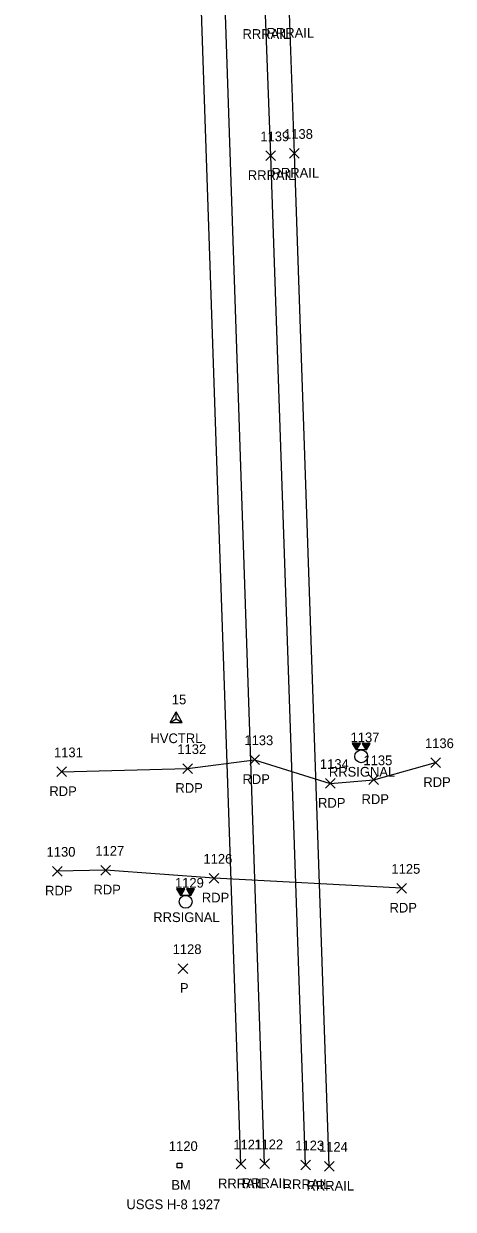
# Model space of a CAD drawing. Extents: x 1754529 to 1755810, y 621660 to 624656.
# Drawn here: x 1755604.2 to 1755692.7, y 621755.5 to 622000 of the extents above; entities that cross this region are included whole.
import ezdxf

# ---------------------------------------------------------------- set-up
doc = ezdxf.new("R2010")
doc.units = 0
for name, color, linetype in [('C_A', 7, 'Continuous'), ('C_C', 7, 'Continuous'), ('C_I', 7, 'Continuous'), ('CPBM', 7, 'Continuous'), ('CPSM', 7, 'Continuous'), ('D_A', 7, 'Continuous'), ('D_I', 7, 'Continuous'), ('D_TIC', 7, 'Continuous'), ('Level 14', 7, 'Continuous'), ('P_A', 7, 'Continuous'), ('P_I', 7, 'Continuous'), ('PET', 7, 'Continuous'), ('R_A', 7, 'Continuous'), ('R_I', 7, 'Continuous'), ('R_TIC', 7, 'Continuous'), ('RR', 7, 'Continuous'), ('TCSH', 7, 'Continuous')]:
    doc.layers.add(name, color=color, linetype=linetype)

msp = doc.modelspace()

# ---------------------------------------------------------------- linework, layer by layer
at = {"layer": 'CPBM'}
for p, q in [((1755635.82, 621764), (1755635.82, 621765)), ((1755635.82, 621765), (1755636.82, 621765)), ((1755636.32, 621764.5), (1755636.32, 621764.5)), ((1755636.32, 621764.5), (1755636.32, 621764.5)), ((1755636.82, 621765), (1755636.82, 621764)), ((1755636.82, 621764), (1755635.82, 621764))]:
    msp.add_line(p, q, dxfattribs=at)
at = {"layer": 'CPSM'}
for p, q in [((1755634.38, 621855.89), (1755635.63, 621858.06)), ((1755636.88, 621855.89), (1755635.63, 621858.06)), ((1755635.63, 621856.61), (1755635.63, 621858.06)), ((1755634.38, 621855.89), (1755635.63, 621856.61)), ((1755634.38, 621855.89), (1755636.88, 621855.89)), ((1755635.63, 621856.61), (1755635.63, 621856.61)), ((1755635.63, 621856.61), (1755636.88, 621855.89))]:
    msp.add_line(p, q, dxfattribs=at)
at = {"layer": 'D_TIC'}
for points in [[(1755636.01, 621804.12), (1755638.01, 621806.12)], [(1755638.01, 621804.12), (1755636.01, 621806.12)]]:
    msp.add_lwpolyline(points, dxfattribs=at)
at = {"layer": 'Level 14'}
for points in [[(1755650.79, 621847.19), (1755652.79, 621849.19)], [(1755652.79, 621847.19), (1755650.79, 621849.19)], [(1755688.05, 621846.58), (1755690.05, 621848.58)], [(1755690.05, 621846.58), (1755688.05, 621848.58)], [(1755611.01, 621844.7), (1755613.01, 621846.7)], [(1755613.01, 621844.7), (1755611.01, 621846.7)], [(1755636.98, 621845.36), (1755638.98, 621847.36)], [(1755638.98, 621845.36), (1755636.98, 621847.36)], [(1755666.36, 621842.3), (1755668.36, 621844.3)], [(1755668.36, 621842.3), (1755666.36, 621844.3)], [(1755675.33, 621843.06), (1755677.33, 621845.06)], [(1755677.33, 621843.06), (1755675.33, 621845.06)], [(1755610.13, 621824.19), (1755612.13, 621826.19)], [(1755612.13, 621824.19), (1755610.13, 621826.19)], [(1755620.09, 621824.4), (1755622.09, 621826.4)], [(1755622.09, 621824.4), (1755620.09, 621826.4)], [(1755642.42, 621822.75), (1755644.42, 621824.75)], [(1755644.42, 621822.75), (1755642.42, 621824.75)], [(1755681.08, 621820.67), (1755683.08, 621822.67)], [(1755683.08, 621820.67), (1755681.08, 621822.67)]]:
    msp.add_lwpolyline(points, dxfattribs=at)
at = {"layer": 'PET'}
for points in [[(1755612.01, 621845.7), (1755637.98, 621846.36), (1755651.79, 621848.19), (1755667.36, 621843.3), (1755676.33, 621844.06), (1755689.05, 621847.58)], [(1755682.08, 621821.67), (1755643.42, 621823.75), (1755621.09, 621825.4), (1755611.13, 621825.19)]]:
    msp.add_lwpolyline(points, dxfattribs=at)
at = {"layer": 'R_TIC'}
for points in [[(1755654.09, 621971.73), (1755656.09, 621973.73)], [(1755656.09, 621971.73), (1755654.09, 621973.73)], [(1755658.97, 621972.23), (1755660.97, 621974.23)], [(1755660.97, 621972.23), (1755658.97, 621974.23)], [(1755647.95, 621763.81), (1755649.95, 621765.81)], [(1755649.95, 621763.81), (1755647.95, 621765.81)], [(1755652.84, 621763.86), (1755654.84, 621765.86)], [(1755654.84, 621763.86), (1755652.84, 621765.86)], [(1755661.28, 621763.64), (1755663.28, 621765.64)], [(1755663.28, 621763.64), (1755661.28, 621765.64)], [(1755666.17, 621763.34), (1755668.17, 621765.34)], [(1755668.17, 621763.34), (1755666.17, 621765.34)]]:
    msp.add_lwpolyline(points, dxfattribs=at)
at = {"layer": 'RR'}
for points in [[(1755648.95, 621764.81), (1755636.45, 622131.43), (1755613.67, 622787.88), (1755609.16, 622923.97), (1755607.65, 622970.2), (1755606.39, 623016.18), (1755605.63, 623052.66), (1755604.97, 623087.09), (1755604.49, 623127.28), (1755604.22, 623170.71)], [(1755653.84, 621764.86), (1755641.42, 622131.55), (1755638.13, 622228.47), (1755618.69, 622787.98), (1755614.09, 622923.65), (1755612.57, 622970.4), (1755611.33, 623016.44), (1755610.51, 623052.88), (1755609.89, 623087.03), (1755609.4, 623127.16), (1755609.16, 623170.67)], [(1755662.28, 621764.64), (1755655.09, 621972.73), (1755653.99, 622001.85), (1755652.5, 622031.16), (1755650.07, 622061.71), (1755646.07, 622096.87), (1755643.03, 622118.54), (1755641.42, 622131.55), (1755640.21, 622141.03), (1755638.59, 622155.76), (1755636.38, 622179.34), (1755634.79, 622202.25), (1755634.18, 622214.39), (1755633.72, 622228.52)], [(1755667.17, 621764.34), (1755659.97, 621973.23), (1755658.94, 622002.1), (1755657.45, 622031.87), (1755654.93, 622062.34), (1755650.95, 622097.56), (1755648.07, 622118.8), (1755646.48, 622130.79), (1755643.53, 622155.97), (1755641.37, 622178.94), (1755639.7, 622202.38), (1755638.13, 622228.47)]]:
    msp.add_lwpolyline(points, dxfattribs=at)
at = {"layer": 'TCSH'}
for p, q in [((1755673.57, 621851.55), (1755671.9, 621851.55)), ((1755671.9, 621851.55), (1755672.67, 621850.21)), ((1755674.83, 621850.21), (1755672.67, 621850.21)), ((1755672.8, 621850.21), (1755673.57, 621851.55)), ((1755675.6, 621851.55), (1755673.94, 621851.55)), ((1755673.94, 621851.55), (1755674.71, 621850.21)), ((1755674.83, 621850.21), (1755675.6, 621851.55)), ((1755673.75, 621848.88), (1755673.75, 621848.88)), ((1755637.39, 621821.56), (1755635.72, 621821.56)), ((1755635.72, 621821.56), (1755636.49, 621820.22)), ((1755636.62, 621820.22), (1755637.39, 621821.56)), ((1755639.42, 621821.56), (1755637.76, 621821.56)), ((1755637.76, 621821.56), (1755638.53, 621820.22)), ((1755638.66, 621820.22), (1755639.42, 621821.56)), ((1755638.66, 621820.22), (1755636.49, 621820.22)), ((1755637.57, 621818.89), (1755637.57, 621818.89))]:
    msp.add_line(p, q, dxfattribs=at)
for points in [[(1755671.95, 621851.47), (1755673.52, 621851.47)], [(1755672.02, 621851.34), (1755673.45, 621851.34)], [(1755672.1, 621851.2), (1755673.37, 621851.2)], [(1755672.18, 621851.07), (1755673.29, 621851.07)], [(1755672.25, 621850.94), (1755673.22, 621850.94)], [(1755672.33, 621850.8), (1755673.14, 621850.8)], [(1755672.41, 621850.67), (1755673.06, 621850.67)], [(1755672.48, 621850.54), (1755672.98, 621850.54)], [(1755672.56, 621850.4), (1755672.91, 621850.4)], [(1755672.64, 621850.27), (1755672.83, 621850.27)], [(1755673.96, 621851.5), (1755675.57, 621851.5)], [(1755674.04, 621851.36), (1755675.5, 621851.36)], [(1755674.12, 621851.23), (1755675.42, 621851.23)], [(1755674.19, 621851.1), (1755675.34, 621851.1)], [(1755674.27, 621850.96), (1755675.27, 621850.96)], [(1755674.35, 621850.83), (1755675.19, 621850.83)], [(1755674.43, 621850.7), (1755675.11, 621850.7)], [(1755674.5, 621850.56), (1755675.04, 621850.56)], [(1755674.58, 621850.43), (1755674.96, 621850.43)], [(1755674.66, 621850.3), (1755674.88, 621850.3)], [(1755635.77, 621821.48), (1755637.35, 621821.48)], [(1755635.84, 621821.35), (1755637.27, 621821.35)], [(1755635.92, 621821.21), (1755637.19, 621821.21)], [(1755636, 621821.08), (1755637.12, 621821.08)], [(1755636.08, 621820.95), (1755637.04, 621820.95)], [(1755636.15, 621820.81), (1755636.96, 621820.81)], [(1755636.23, 621820.68), (1755636.88, 621820.68)], [(1755637.79, 621821.51), (1755639.4, 621821.51)], [(1755637.86, 621821.37), (1755639.32, 621821.37)], [(1755637.94, 621821.24), (1755639.24, 621821.24)], [(1755638.02, 621821.11), (1755639.17, 621821.11)], [(1755638.09, 621820.97), (1755639.09, 621820.97)], [(1755638.17, 621820.84), (1755639.01, 621820.84)], [(1755638.25, 621820.71), (1755638.94, 621820.71)], [(1755636.31, 621820.55), (1755636.81, 621820.55)], [(1755636.38, 621820.41), (1755636.73, 621820.41)], [(1755636.46, 621820.28), (1755636.65, 621820.28)], [(1755638.32, 621820.57), (1755638.86, 621820.57)], [(1755638.4, 621820.44), (1755638.78, 621820.44)], [(1755638.48, 621820.31), (1755638.7, 621820.31)]]:
    msp.add_lwpolyline(points, dxfattribs=at)
for centre in [(1755673.75, 621848.88), (1755637.57, 621818.89)]:
    msp.add_circle(centre, 1.33, dxfattribs=at)

# ---------------------------------------------------------------- texts
at = {"layer": 'C_A'}
for s, p in [('HVCTRL', (1755630.32, 621851.61)), ('BM', (1755634.64, 621759.5))]:
    msp.add_text(s, height=2, dxfattribs=at).set_placement(p)
at = {"layer": 'C_C'}
msp.add_text('USGS H-8 1927', height=2, dxfattribs=at).set_placement((1755625.38, 621755.5))
at = {"layer": 'C_I'}
for s, p in [('15', (1755634.73, 621859.61)), ('1120', (1755634.11, 621767.5))]:
    msp.add_text(s, height=2, dxfattribs=at).set_placement(p)
at = {"layer": 'D_A'}
msp.add_text('P', height=2, dxfattribs=at).set_placement((1755636.39, 621800.12))
at = {"layer": 'D_I'}
msp.add_text('1128', height=2, dxfattribs=at).set_placement((1755634.89, 621808.12))
at = {"layer": 'P_A'}
for p in [(1755649.28, 621843.19), (1755609.5, 621840.7), (1755635.47, 621841.36), (1755686.54, 621842.58), (1755664.85, 621838.3), (1755673.81, 621839.06), (1755608.62, 621820.19), (1755618.58, 621820.4), (1755640.91, 621818.75), (1755679.57, 621816.67)]:
    msp.add_text('RDP', height=2, dxfattribs=at).set_placement(p)
at = {"layer": 'P_I'}
for s, p in [('1133', (1755649.67, 621851.19)), ('1136', (1755686.87, 621850.58)), ('1131', (1755610.45, 621848.7)), ('1132', (1755635.86, 621849.36)), ('1134', (1755665.23, 621846.3)), ('1135', (1755674.2, 621847.06)), ('1130', (1755608.92, 621828.19)), ('1127', (1755618.97, 621828.4)), ('1126', (1755641.24, 621826.75)), ('1125', (1755679.96, 621824.67))]:
    msp.add_text(s, height=2, dxfattribs=at).set_placement(p)
at = {"layer": 'R_A'}
for s, p in [('RRRAIL', (1755649.28, 621996.85)), ('RRRAIL', (1755654.23, 621997.1)), ('RRRAIL', (1755655.26, 621968.23)), ('RRRAIL', (1755650.38, 621967.73)), ('RRSIGNAL', (1755667.08, 621844.7)), ('RRSIGNAL', (1755630.9, 621814.71)), ('RRRAIL', (1755644.24, 621759.81)), ('RRRAIL', (1755649.13, 621759.86)), ('RRRAIL', (1755657.57, 621759.64)), ('RRRAIL', (1755662.46, 621759.34))]:
    msp.add_text(s, height=2, dxfattribs=at).set_placement(p)
at = {"layer": 'R_I'}
for s, p in [('1139', (1755652.96, 621975.73)), ('1138', (1755657.84, 621976.23)), ('1137', (1755671.55, 621851.8)), ('1129', (1755635.37, 621821.81)), ('1121', (1755647.39, 621767.81)), ('1122', (1755651.71, 621767.86)), ('1123', (1755660.15, 621767.64)), ('1124', (1755665.04, 621767.34))]:
    msp.add_text(s, height=2, dxfattribs=at).set_placement(p)

doc.saveas('drawing.dxf')
